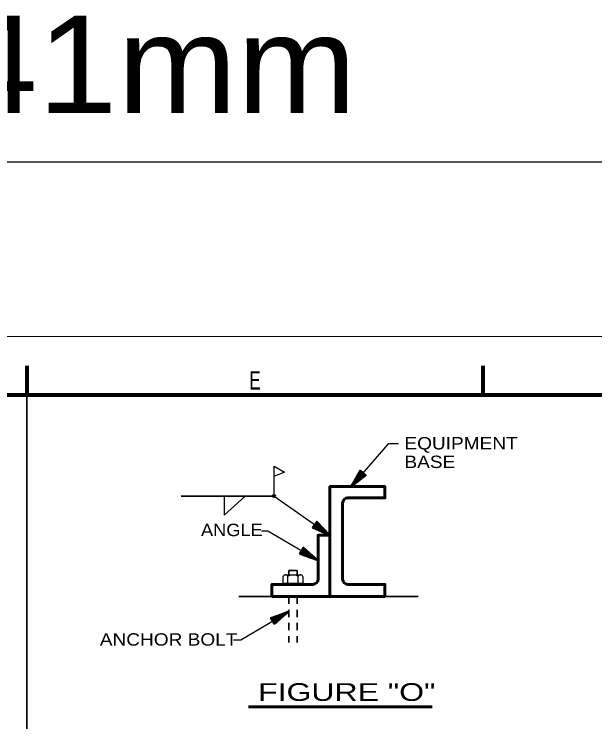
# Model space of a CAD drawing. Extents: x 55 to 190, y 198 to 264.
# Drawn here: x 102.33 to 114.24, y 249.95 to 264.46 of the extents above; entities that cross this region are included whole.
import ezdxf
from ezdxf.enums import TextEntityAlignment as Align

# ---------------------------------------------------------------- set-up
doc = ezdxf.new("R2010")
doc.units = 0
doc.header["$LTSCALE"] = 0.1
doc.header["$PDMODE"] = 32
doc.header["$PDSIZE"] = 0.05
doc.linetypes.add('SHORT_DASHED', pattern=[2.7, 1.5, -1.2])
for name, color, linetype, lineweight in [('1', 7, 'Continuous', 25), ('2', 7, 'Continuous', 40), ('3', 7, 'Continuous', 25)]:
    doc.layers.add(name, color=color, linetype=linetype, lineweight=lineweight)

msp = doc.modelspace()

# ---------------------------------------------------------------- linework, layer by layer
at = {"layer": '1', "lineweight": 80}
for p, q in [((102.5927, 257.2525), (102.5927, 256.6525)), ((111.9427, 257.2525), (111.9427, 256.6525))]:
    msp.add_line(p, q, dxfattribs=at)
at = {"layer": '1', "lineweight": 13}
msp.add_lwpolyline([(62.4915, 257.8525), (146.5927, 257.8525), (146.5927, 198.4512), (62.4915, 198.4512)], close=True, dxfattribs=at)
at = {"layer": '1', "lineweight": 80}
msp.add_lwpolyline([(65.1915, 256.6525), (145.3927, 256.6525), (145.3927, 199.6512), (65.1915, 199.6512)], close=True, dxfattribs=at)
at = {"layer": '2', "lineweight": 35}
for p, q in [((102.5927, 256.6525), (102.5927, 199.6512)), ((106.935, 252.5179), (110.6172, 252.5179))]:
    msp.add_line(p, q, dxfattribs=at)
at = {"layer": '2'}
for p, q in [((109.2316, 254.7722), (109.4417, 255.0968)), ((109.2316, 254.7722), (109.4417, 255.0968)), ((109.2316, 254.7722), (109.4581, 255.0831)), ((109.2316, 254.7722), (109.4581, 255.0831)), ((109.2316, 254.7722), (109.4705, 255.0714)), ((109.2316, 254.7722), (109.4705, 255.0714)), ((109.484, 255.0598), (109.2316, 254.7722)), ((109.484, 255.0598), (109.2316, 254.7722)), ((109.2316, 254.7722), (109.4983, 255.0468)), ((109.2316, 254.7722), (109.4983, 255.0468)), ((109.2316, 254.7722), (109.5263, 255.0222)), ((109.2316, 254.7722), (109.5263, 255.0222)), ((108.8046, 253.7766), (108.459, 253.9501)), ((108.8046, 253.7766), (108.4709, 253.9679)), ((108.8046, 253.7766), (108.4812, 253.9814)), ((108.4913, 253.9962), (108.8046, 253.7766)), ((108.8046, 253.7766), (108.5024, 254.0118)), ((108.8046, 253.7766), (108.5238, 254.0422)), ((108.5569, 253.2649), (108.2561, 253.5072)), ((108.5569, 253.2649), (108.1987, 253.4101)), ((108.5569, 253.2649), (108.209, 253.4289)), ((108.5569, 253.2649), (108.2182, 253.4432)), ((108.227, 253.4588), (108.5569, 253.2649)), ((108.5569, 253.2649), (108.237, 253.4752)), ((107.9608, 252.2131), (107.6028, 252.0674)), ((107.9608, 252.2131), (107.6219, 252.0351)), ((107.6314, 252.0184), (107.9608, 252.2131)), ((107.9608, 252.2131), (107.6407, 252.0031)), ((107.9608, 252.2131), (107.6489, 251.9882)), ((107.9608, 252.2131), (107.6602, 251.97))]:
    msp.add_line(p, q, dxfattribs=at)
at = {"layer": '2', "lineweight": 25}
for p, q in [((107.661, 254.5806), (105.7558, 254.5806)), ((107.8444, 252.792), (107.8444, 252.9347)), ((107.896, 252.9656), (108.2024, 252.9656)), ((107.946, 252.792), (107.946, 252.9347)), ((108.1516, 252.792), (108.1516, 252.9347)), ((108.2537, 252.792), (108.2537, 252.9333)), ((107.8444, 252.792), (108.2537, 252.792))]:
    msp.add_line(p, q, dxfattribs=at)
at = {"layer": '2', "lineweight": 60}
for p, q in [((109.0662, 254.4362), (109.0662, 252.8754)), ((109.9325, 252.5179), (107.6163, 252.5179)), ((107.1387, 250.2597), (110.9038, 250.2597))]:
    msp.add_line(p, q, dxfattribs=at)
at = {"layer": '2', "linetype": 'SHORT_DASHED', "lineweight": 35}
for p, q in [((107.9653, 252.5179), (107.9653, 251.5789)), ((108.1333, 252.5179), (108.1333, 251.5789))]:
    msp.add_line(p, q, dxfattribs=at)
at = {"layer": '2', "lineweight": 25}
for points in [[(110.2132, 255.6488), (110.0029, 255.6488), (109.2316, 254.7722)], [(107.661, 254.5806), (107.661, 255.1921), (107.8774, 255.0717), (107.6732, 254.9875)], [(105.7558, 254.5806), (107.661, 254.5806), (108.8046, 253.7766)], [(106.6381, 254.5806), (106.6381, 254.1896), (107.0694, 254.5806)], [(107.3999, 253.8697), (107.5314, 253.8697), (108.5569, 253.2649)], [(106.8302, 251.6348), (106.9792, 251.6348), (107.9608, 252.2131)]]:
    msp.add_lwpolyline(points, dxfattribs=at)
at = {"layer": '2'}
for points in [[(109.4268, 255.1095), (109.5417, 255.0085), (109.2316, 254.7722)], [(109.4268, 255.1095), (109.2316, 254.7722), (109.5126, 255.0347)], [(109.4268, 255.1095), (109.5417, 255.0085), (109.2316, 254.7722)], [(109.4268, 255.1095), (109.2316, 254.7722), (109.5126, 255.0347)], [(108.4479, 253.9343), (108.5363, 254.0591), (108.8046, 253.7766)], [(108.4479, 253.9343), (108.8046, 253.7766), (108.5132, 254.0274)], [(108.1889, 253.3934), (108.2667, 253.5252), (108.5569, 253.2649)], [(108.1889, 253.3934), (108.5569, 253.2649), (108.2463, 253.4916)], [(107.67, 251.9533), (107.5925, 252.0853), (107.9608, 252.2131)], [(107.67, 251.9533), (107.9608, 252.2131), (107.6121, 252.0512)]]:
    msp.add_lwpolyline(points, dxfattribs=at)
at = {"layer": '2', "lineweight": 60}
for points in [[(108.8046, 252.5179), (108.8046, 254.7735), (109.9325, 254.7735), (109.9325, 254.542), (109.1721, 254.542)], [(108.5627, 252.8754), (108.5627, 253.7766), (108.8046, 253.7766)], [(107.6163, 252.5179), (107.6163, 252.7696), (108.4569, 252.7696)], [(109.1721, 252.7696), (109.9325, 252.7696), (109.9325, 252.5179)]]:
    msp.add_lwpolyline(points, dxfattribs=at)
at = {"layer": '2', "lineweight": 35}
msp.add_lwpolyline([(108.1333, 252.9664), (108.1333, 253.0524), (107.9653, 253.0524), (107.9653, 252.9664)], dxfattribs=at)
at = {"layer": '2', "lineweight": 60}
for centre, start, end in [((109.1721, 254.4362), 90, 180), ((108.4569, 252.8754), 270, 0), ((109.1721, 252.8754), 180, 270)]:
    msp.add_arc(centre, 0.1058, start, end, dxfattribs=at)
at = {"layer": '2', "lineweight": 25}
for centre, radius, start, end in [((107.8953, 252.9083), 0.0572, 27.8877, 152.03419), ((108.0487, 252.7764), 0.189, 57.00616, 122.94297), ((108.2021, 252.9079), 0.0572, 26.78269, 151.8391)]:
    msp.add_arc(centre, radius, start, end, dxfattribs=at)
at = {"layer": '2'}
msp.add_point((107.661, 254.5806), dxfattribs=at)
at = {"layer": '3'}
msp.add_line((62.4915, 261.4312), (146.5927, 261.4312), dxfattribs=at)

# ---------------------------------------------------------------- texts
at = {"layer": '1', "width": 0.7}
msp.add_text('E', height=0.375, dxfattribs=at).set_placement((107.2679, 256.765), align=Align.CENTER)
at = {"layer": '2', "width": 1.15}
for s, p in [('EQUIPMENT', (110.3333, 255.5358)), ('BASE', (110.3333, 255.1548)), ('ANCHOR BOLT', (104.0878, 251.5128))]:
    msp.add_text(s, height=0.254, dxfattribs=at).set_placement(p)
at = {"layer": '2', "width": 1.1}
msp.add_text('ANGLE', height=0.254, dxfattribs=at).set_placement((107.429, 253.7583), align=Align.RIGHT)
at = {"layer": '2', "width": 1.35}
msp.add_text('FIGURE "O"', height=0.3633, dxfattribs=at).set_placement((109.1503, 250.3801), align=Align.CENTER)
at = {"layer": '3', "width": 1.1}
msp.add_text('841mm', height=2, dxfattribs=at).set_placement((99.5415, 262.4312))

doc.saveas('drawing.dxf')
